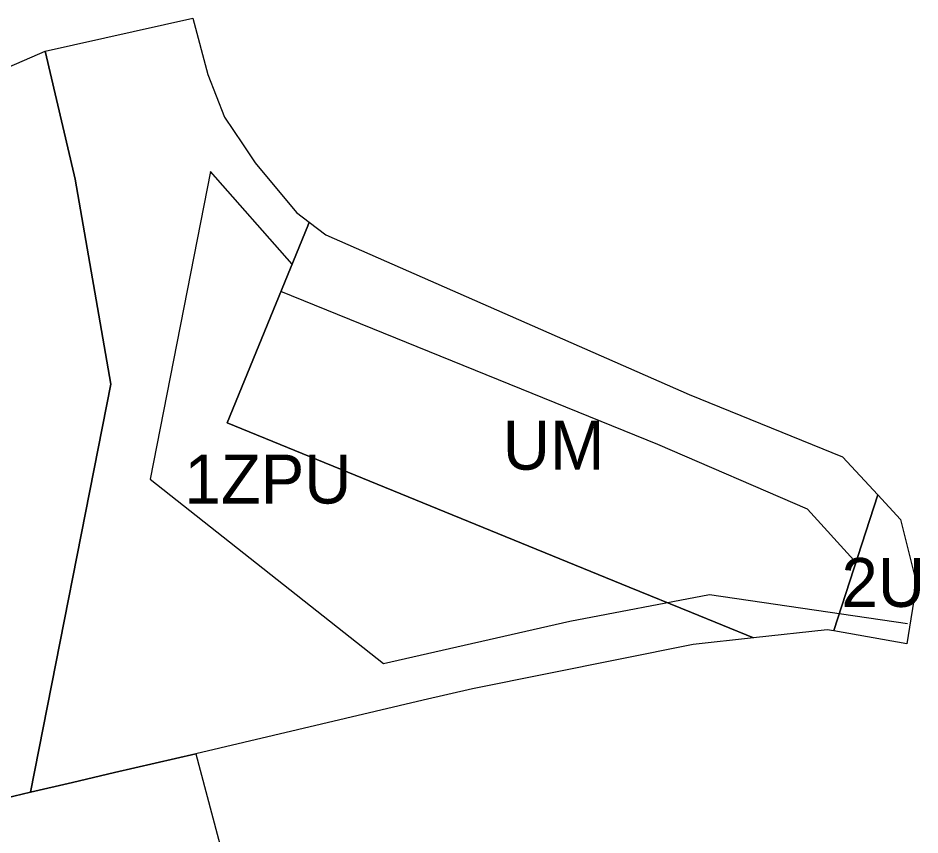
# Model space of a CAD drawing. Extents: x 7428426 to 7429844, y 5541841 to 5543687.
# Drawn here: x 7429266.8 to 7429488.3, y 5542703.3 to 5542903.8 of the extents above; entities that cross this region are included whole.
import ezdxf

# ---------------------------------------------------------------- set-up
doc = ezdxf.new("R2010")
doc.units = 0
for name, color, linetype in [('1', 7, 'Continuous'), ('linie_rozgraniczajace', 7, 'Continuous'), ('linie_zabudowy_nieprzekraczalne', 7, 'Continuous'), ('oznaczenia_przeznaczen', 7, 'Continuous')]:
    doc.layers.add(name, color=color, linetype=linetype)

msp = doc.modelspace()

# ---------------------------------------------------------------- linework, layer by layer
at = {"layer": '1'}
for points in [[(7429334.17, 5542843.41), (7429314.13, 5542866.09), (7429299.24, 5542790.59), (7429356.58, 5542745.38), (7429402.36, 5542755.71), (7429436.68, 5542762.31), (7429485.28, 5542755.16)], [(7429472.13, 5542770.7), (7429460.73, 5542783.28), (7429423.99, 5542799.08), (7429331.37, 5542836.68)]]:
    msp.add_lwpolyline(points, dxfattribs=at)
at = {"layer": 'linie_rozgraniczajace'}
for points in [[(7429269.92, 5542713.77), (7429269.92, 5542713.79), (7429289.65, 5542813.89), (7429280.86, 5542864.27), (7429280.62, 5542865.31), (7429273.48, 5542895.69), (7429309.75, 5542903.8), (7429313.41, 5542889.92), (7429317.57, 5542879.43), (7429321.97, 5542872.91), (7429325.1, 5542868.27), (7429335.2, 5542856.03), (7429338.32, 5542853.67), (7429337.96, 5542852.8), (7429318.19, 5542804.45), (7429382.83, 5542778.04), (7429416.91, 5542764.11), (7429432.19, 5542757.87), (7429447.46, 5542751.63), (7429432.62, 5542749.99), (7429378.42, 5542739.11), (7429366.36, 5542736.35), (7429310.47, 5542723.2), (7429305.48, 5542722.04), (7429300.49, 5542720.88), (7429295.5, 5542719.72), (7429290.51, 5542718.57), (7429280.21, 5542716.17)], [(7429269.92, 5542713.77), (7429269.92, 5542713.79), (7429289.65, 5542813.89), (7429280.86, 5542864.27), (7429280.62, 5542865.31), (7429273.48, 5542895.69), (7429309.75, 5542903.8), (7429313.41, 5542889.92), (7429317.57, 5542879.43), (7429321.97, 5542872.91), (7429325.1, 5542868.27), (7429335.2, 5542856.03), (7429338.32, 5542853.67), (7429337.96, 5542852.8), (7429318.19, 5542804.45), (7429382.83, 5542778.04), (7429416.91, 5542764.11), (7429432.19, 5542757.87), (7429447.46, 5542751.63), (7429432.62, 5542749.99), (7429378.42, 5542739.11), (7429366.36, 5542736.35), (7429310.47, 5542723.2), (7429305.48, 5542722.04), (7429300.49, 5542720.88), (7429295.5, 5542719.72), (7429290.51, 5542718.57), (7429280.21, 5542716.17)], [(7429318.19, 5542804.45), (7429337.96, 5542852.8), (7429338.32, 5542853.67), (7429342.44, 5542850.55), (7429431.63, 5542811.4), (7429469.31, 5542796.12), (7429477.96, 5542786.75), (7429467.17, 5542753.42), (7429467.15, 5542753.34), (7429465.55, 5542753.62), (7429447.46, 5542751.63), (7429432.19, 5542757.87), (7429416.91, 5542764.11), (7429382.83, 5542778.04)], [(7429318.19, 5542804.45), (7429337.96, 5542852.8), (7429338.32, 5542853.67), (7429342.44, 5542850.55), (7429431.63, 5542811.4), (7429469.31, 5542796.12), (7429477.96, 5542786.75), (7429467.17, 5542753.42), (7429467.15, 5542753.34), (7429465.55, 5542753.62), (7429447.46, 5542751.63), (7429432.19, 5542757.87), (7429416.91, 5542764.11), (7429382.83, 5542778.04)], [(7429467.15, 5542753.34), (7429467.17, 5542753.42), (7429477.96, 5542786.75), (7429483.53, 5542780.7), (7429487.48, 5542764.98), (7429485.12, 5542750.21)], [(7429467.15, 5542753.34), (7429467.17, 5542753.42), (7429477.96, 5542786.75), (7429483.53, 5542780.7), (7429487.48, 5542764.98), (7429485.12, 5542750.21)], [(7429252.71, 5542709.77), (7429263.73, 5542712.33), (7429269.92, 5542713.77), (7429280.21, 5542716.17), (7429290.51, 5542718.57), (7429295.5, 5542719.72), (7429300.49, 5542720.88), (7429305.48, 5542722.04), (7429310.47, 5542723.2), (7429323.78, 5542673.23), (7429268.47, 5542660.17), (7429266.16, 5542659.62), (7429265.93, 5542659.56), (7429260.77, 5542658.35), (7429259, 5542669.65)], [(7429252.71, 5542709.77), (7429263.73, 5542712.33), (7429269.92, 5542713.77), (7429280.21, 5542716.17), (7429290.51, 5542718.57), (7429295.5, 5542719.72), (7429300.49, 5542720.88), (7429305.48, 5542722.04), (7429310.47, 5542723.2), (7429323.78, 5542673.23), (7429268.47, 5542660.17), (7429266.16, 5542659.62), (7429265.93, 5542659.56), (7429260.77, 5542658.35), (7429259, 5542669.65)]]:
    msp.add_lwpolyline(points, close=True, dxfattribs=at)
msp.add_lwpolyline([(7429255.76, 5542887.98), (7429273.48, 5542895.69), (7429280.62, 5542865.31), (7429280.86, 5542864.27), (7429289.65, 5542813.89), (7429269.92, 5542713.79), (7429269.92, 5542713.77), (7429263.73, 5542712.33)], dxfattribs=at)
msp.add_lwpolyline([(7429255.76, 5542887.98), (7429273.48, 5542895.69), (7429280.62, 5542865.31), (7429280.86, 5542864.27), (7429289.65, 5542813.89), (7429269.92, 5542713.79), (7429269.92, 5542713.77), (7429263.73, 5542712.33)], dxfattribs=at)
at = {"layer": 'linie_zabudowy_nieprzekraczalne'}
for points in [[(7429334.17, 5542843.41), (7429314.13, 5542866.09), (7429299.24, 5542790.59), (7429356.58, 5542745.38), (7429402.36, 5542755.71), (7429436.68, 5542762.31), (7429485.28, 5542755.16)], [(7429334.17, 5542843.41), (7429314.13, 5542866.09), (7429299.24, 5542790.59), (7429356.58, 5542745.38), (7429402.36, 5542755.71), (7429436.68, 5542762.31), (7429485.28, 5542755.16)], [(7429472.13, 5542770.7), (7429460.73, 5542783.28), (7429423.99, 5542799.08), (7429331.37, 5542836.68)], [(7429472.13, 5542770.7), (7429460.73, 5542783.28), (7429423.99, 5542799.08), (7429331.37, 5542836.68)]]:
    msp.add_lwpolyline(points, dxfattribs=at)

# ---------------------------------------------------------------- texts
at = {"layer": 'oznaczenia_przeznaczen'}
for s, p in [('UM', (7429385.88, 5542792.93)), ('UM', (7429385.88, 5542792.93)), ('UM', (7429385.88, 5542792.93)), ('UM', (7429385.88, 5542792.93)), ('1ZPU', (7429307.7, 5542784.62)), ('1ZPU', (7429307.7, 5542784.62)), ('1ZPU', (7429307.7, 5542784.62)), ('1ZPU', (7429307.7, 5542784.62)), ('2U', (7429469.06, 5542759.25)), ('2U', (7429469.06, 5542759.25)), ('2U', (7429469.06, 5542759.25)), ('2U', (7429469.06, 5542759.25))]:
    msp.add_text(s, height=12, dxfattribs=at).set_placement(p)

doc.saveas('drawing.dxf')
